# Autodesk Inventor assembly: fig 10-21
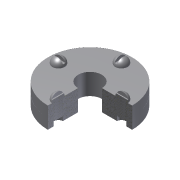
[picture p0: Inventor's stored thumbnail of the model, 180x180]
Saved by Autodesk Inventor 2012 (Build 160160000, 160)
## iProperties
Shininess: 64.0
Angle Display Precision: 2
Document Length Units: 11269
Document Angle Units: 11279
Document Time Units: 11290
Document Mass Units: 11283
Document Length Units Precision: 3
Document Angle Units Precision: 2
Created: 2002-02
Part Number: fig 10-21
Document SubType Name: Assembly
Designer: ***
Density: 0.0
Volumn: 0.0
Area: 0.0
PropertySet Name: Model Information
Control State: 0
Master: False
Checked Out: False
Author: ***
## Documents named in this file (3)
- C:\Users\CadCim\Documents\SAILESH\inventor-2011-fact-prt\c10-inv-2011-prt\c10_inv_2012_prt\fig 10-21.iam
- C:\Users\CadCim\Documents\SAILESH\inventor-2011-fact-prt\c10-inv-2011-prt\c10_inv_2012_prt\Screw.ipt
- C:\Users\CadCim\Documents\SAILESH\inventor-2011-fact-prt\c10-inv-2011-prt\c10_inv_2012_prt\test.ipt
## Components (6 placed, 2 different names)
1. test:1 — Insert:1, Insert:2
2. test:2 — Insert:1
3. Screw:1 — Angle:1, Insert:2
4. Screw:11
5. Screw:12
6. Screw:13
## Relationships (3: Insert 2, Angle 1)
- Insert:1: test:1 ↔ test:2
- Angle:1: Screw:1
- Insert:2: test:1 ↔ Screw:1
